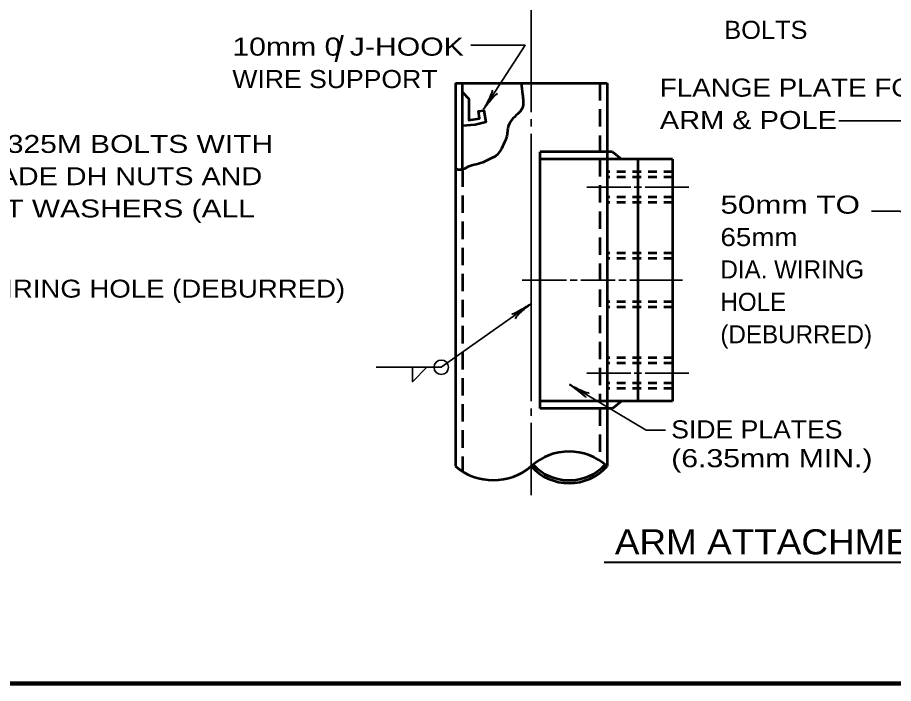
# Model space of a CAD drawing. Extents: x -39 to 816, y -16 to 528.
# Drawn here: x 240.6 to 387.3, y -4.2 to 107.2 of the extents above; entities that cross this region are included whole.
import ezdxf
from ezdxf.enums import TextEntityAlignment as Align

# ---------------------------------------------------------------- set-up
doc = ezdxf.new("R2010")
doc.units = 0
doc.header["$LTSCALE"] = 0.97
doc.linetypes.add('MEDIUM_DASHED', pattern=[4.5, 3, -1.5])
doc.linetypes.add('SHORT_DASHED', pattern=[2.7, 1.5, -1.2])
doc.layers.add('1', color=7, linetype='Continuous', lineweight=35)

msp = doc.modelspace()

# ---------------------------------------------------------------- linework, layer by layer
at = {"layer": '1'}
for p, q in [((326.6047, 122.8435), (326.6047, 91.3795)), ((326.6047, 90.1795), (326.6047, 88.9555)), ((390.2348, 89.9395), (378.1355, 89.9395)), ((326.6047, 87.7555), (326.6047, 42.9955)), ((335.9407, 78.8275), (343.2607, 78.8275)), ((343.8607, 78.8275), (345.0607, 78.8275)), ((345.6607, 78.8275), (352.9807, 78.8275)), ((325.0927, 63.2515), (332.5087, 63.2515)), ((333.1087, 63.2515), (334.3087, 63.2515)), ((334.9327, 63.2515), (340.6687, 63.2515)), ((341.2687, 63.2515), (342.4927, 63.2515)), ((343.0927, 63.2515), (351.9195, 63.2515)), ((335.9407, 47.6755), (343.2607, 47.6755)), ((343.8607, 47.6755), (345.0607, 47.6755)), ((345.6607, 47.6755), (352.9807, 47.6755)), ((326.6047, 41.7955), (326.6047, 40.5715)), ((326.6047, 39.3715), (326.6047, 27.2755))]:
    msp.add_line(p, q, dxfattribs=at)
at = {"layer": '1', "lineweight": 53}
for p, q in [((313.9087, 96.2275), (313.9087, 32.0995)), ((313.9087, 96.2275), (339.3007, 96.2275)), ((315.1087, 81.7795), (315.1087, 96.2275)), ((328.1167, 41.7955), (328.1167, 84.7315)), ((340.2127, 84.7315), (328.1167, 84.7315)), ((340.2127, 84.7315), (341.7247, 83.5075)), ((344.4607, 83.5075), (344.4607, 42.9955)), ((350.2434, 83.5075), (350.2434, 42.9955)), ((341.7247, 42.9955), (340.2127, 41.7955)), ((340.2127, 41.7955), (328.1167, 41.7955))]:
    msp.add_line(p, q, dxfattribs=at)
at = {"layer": '1', "linetype": 'MEDIUM_DASHED', "lineweight": 53}
for p, q in [((338.1007, 96.2275), (338.1007, 84.7315)), ((338.1007, 83.5075), (338.1007, 42.9955)), ((315.1087, 81.7795), (315.1087, 31.2355)), ((338.1007, 41.7955), (338.1007, 33.0595))]:
    msp.add_line(p, q, dxfattribs=at)
at = {"layer": '1', "linetype": 'SHORT_DASHED', "lineweight": 53}
for p, q in [((350.2434, 81.3955), (339.3007, 81.3955)), ((350.2434, 80.4835), (339.3007, 80.4835)), ((350.2434, 77.1715), (339.3007, 77.1715)), ((350.2434, 76.2595), (339.3007, 76.2595)), ((350.2434, 67.7875), (339.3007, 67.7875)), ((350.2434, 66.8755), (339.3007, 66.8755)), ((350.2434, 59.6275), (339.3007, 59.6275)), ((350.2434, 58.7155), (339.3007, 58.7155)), ((350.2434, 50.2435), (339.3007, 50.2435)), ((350.2434, 49.3555), (339.3007, 49.3555)), ((350.2434, 46.0195), (339.3007, 46.0195)), ((350.2434, 45.1075), (339.3007, 45.1075))]:
    msp.add_line(p, q, dxfattribs=at)
at = {"layer": '1', "lineweight": 40}
msp.add_line((338.8491, 16.0812), (401.0879, 16.0812), dxfattribs=at)
at = {"layer": '1', "lineweight": 158}
msp.add_line((809.7034, -4.248), (18.1034, -4.248), dxfattribs=at)
at = {"layer": '1'}
for points in [[(318.6367, 91.8355), (325.5727, 102.5635), (316.491, 102.5635)], [(405.0188, 67.7155), (388.3148, 74.7955), (383.5628, 74.7955)], [(326.4701, 59.2261), (311.5421, 48.6901), (300.6701, 48.6901)], [(306.7181, 48.6901), (306.7181, 46.2661), (309.1421, 48.6901)], [(333.0367, 45.8035), (345.8527, 38.1235), (349.1167, 38.1235)]]:
    msp.add_lwpolyline(points, dxfattribs=at)
at = {"layer": '1', "lineweight": 53}
for points in [[(339.3007, 96.2275), (339.3007, 80.4835), (339.3007, 77.1715)], [(315.1087, 94.7155), (316.1887, 93.6355), (316.1887, 90.0115), (317.9647, 90.3235), (317.7727, 91.5235), (318.6607, 91.6675), (318.9967, 89.6755), (317.2447, 89.2675), (315.1087, 89.0995)], [(350.2434, 83.5075), (339.3007, 83.5075), (328.1167, 83.5075)], [(339.3007, 77.1715), (339.3007, 49.3555), (339.3007, 46.0195), (339.3007, 32.0995)], [(350.2434, 42.9955), (339.3007, 42.9955), (328.1167, 42.9955)]]:
    msp.add_lwpolyline(points, dxfattribs=at)
at = {"layer": '1'}
msp.add_circle((311.5505, 48.6782), 1.2096, dxfattribs=at)
at = {"layer": '1', "lineweight": 53}
for centre, radius, start, end in [((332.9581, 25.211), 9.3772, 47.37365, 132.62636), ((332.9581, 38.0389), 8.2831, 223.11119, 316.88881), ((320.2573, 39.6025), 9.8212, 229.71432, 310.28569), ((332.9581, 37.8119), 8.5342, 221.91688, 318.08312)]:
    msp.add_arc(centre, radius, start, end, dxfattribs=at)
at = {"layer": '1', "lineweight": 40}
for centre, major_axis, ratio, start_param, end_param in [((319.0664, 93.1325), (-1.0145, -1.9162), 0.122415, 0.89635335, 3.14159265), ((319.5812, 92.8417), (-1.3323, -1.6685), 0.07063, 3.14071475, 5.41810995), ((325.2274, 58.663), (-1.8574, -1.0532), 0.07063, 6.28230741, 8.55970261), ((325.597, 58.2016), (1.6545, 1.4013), 0.122415, 0.89635335, 3.14159265), ((334.0601, 44.8771), (1.7139, -1.2734), 0.07063, 6.28230741, 8.55970261), ((334.3328, 45.4017), (-1.9504, 0.9472), 0.122415, 0.89635335, 3.14159265)]:
    msp.add_ellipse(centre, major_axis=major_axis, ratio=ratio, start_param=start_param, end_param=end_param, dxfattribs=at)
at = {"layer": '1', "lineweight": 53}
msp.add_spline([(324.9247, 96.2275), (325.1407, 94.3555), (325.1407, 92.0995), (323.2927, 90.0355), (322.6687, 88.5955), (322.5727, 87.6835), (322.1407, 86.3395), (321.4207, 84.8995), (320.7007, 84.0595), (320.1967, 83.7715), (317.4127, 82.6195), (315.9727, 82.2115), (314.8447, 81.7075), (313.9327, 81.8995)], degree=3, dxfattribs=at)

# ---------------------------------------------------------------- texts
at = {"layer": '1'}
for s, height, width, p in [('BOLTS', 3.024, 1.05, (358.9373, 103.6414)), ('10mm 0 J-HOOK', 3.024, 1.25, (276.5611, 100.8341)), ('WIRE SUPPORT', 3.024, 1.1, (276.5611, 95.4101)), ('FLANGE PLATE FOR', 3.024, 1.15, (348.1397, 93.9735)), ('ARM & POLE', 3.024, 1.2, (348.1397, 88.5495)), ('FOUR (4) A 325M BOLTS WITH', 3, 1.25, (210.9466, 84.5554)), ('A 563M, GRADE DH NUTS AND', 3, 1.2, (210.9466, 79.1554)), ('F 436M FLAT WASHERS (ALL', 3, 1.25, (210.9466, 73.7554)), ('50mm TO', 3.024, 1.3, (358.2908, 74.3875)), ('65mm', 3.024, 1.15, (358.2908, 68.9635)), ('65mm DIA. WIRING HOLE (DEBURRED)', 3, 1.15, (209.8302, 60.3357)), ('SIDE PLATES', 3.024, 1.1, (350.0496, 36.7751)), ('(6.35mm MIN.)', 3.024, 1.25, (350.0496, 31.9511)), ('ARM ATTACHMENT', 4.2, 1.1, (340.6125, 17.362))]:
    msp.add_text(s, height=height, dxfattribs=dict(at, width=width)).set_placement(p)
msp.add_text('/', height=4.2, rotation=180, dxfattribs=at).set_placement((294.4509, 104.2126), align=Align.CENTER)
for s, p in [('DIA. WIRING', (358.2908, 63.5395)), ('HOLE', (358.2908, 58.1155)), ('(DEBURRED)', (358.2908, 52.6915))]:
    msp.add_text(s, height=3.024, dxfattribs=at).set_placement(p)

doc.saveas('drawing.dxf')
